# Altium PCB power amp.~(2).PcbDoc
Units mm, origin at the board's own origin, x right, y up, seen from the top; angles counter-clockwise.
Board outline 188.72 x 72.39 mm, 2 copper layers (Top Layer, Bottom Layer); 34 components, 39 nets, 124 pads, 0 vias.
Unrouted connection lines stored in the file: 65.
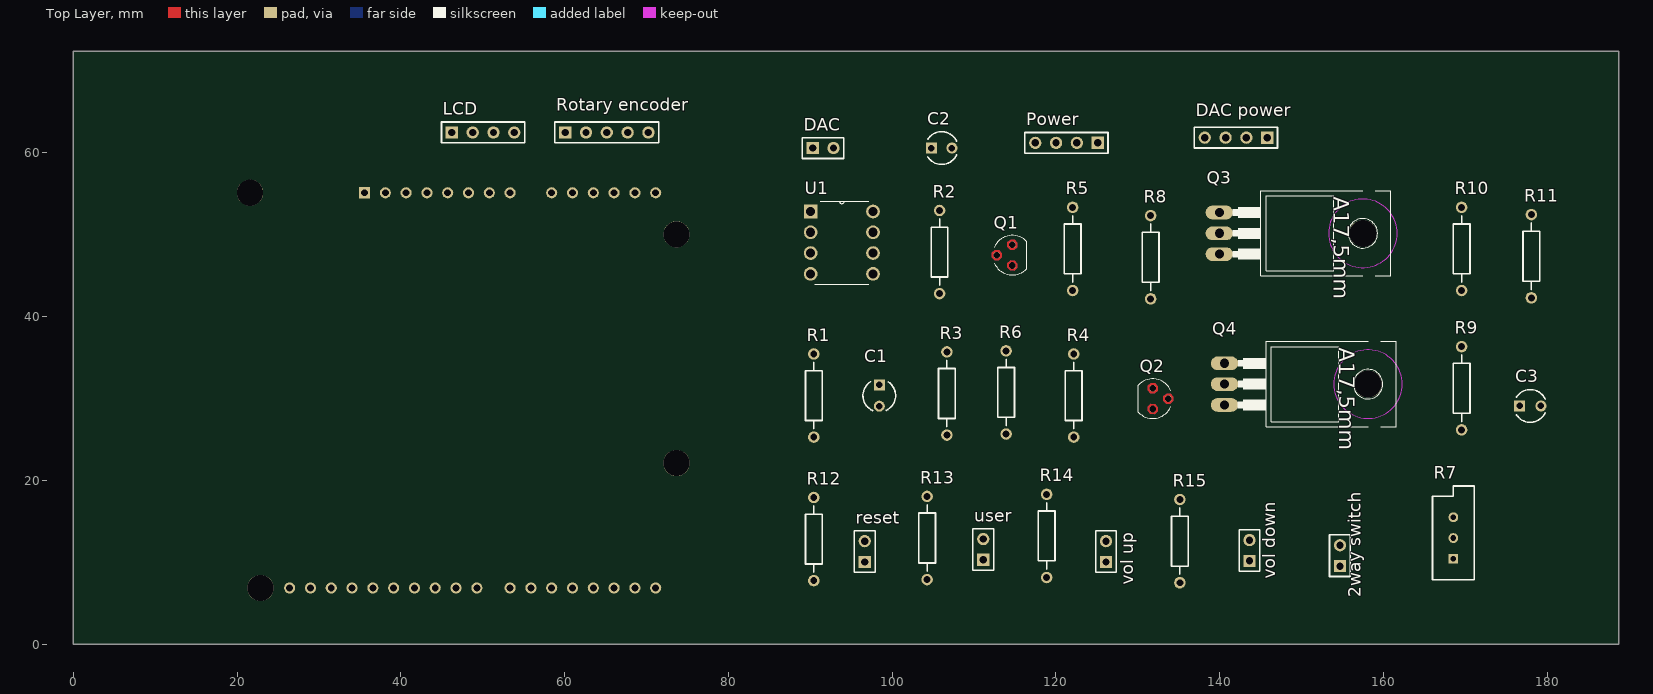
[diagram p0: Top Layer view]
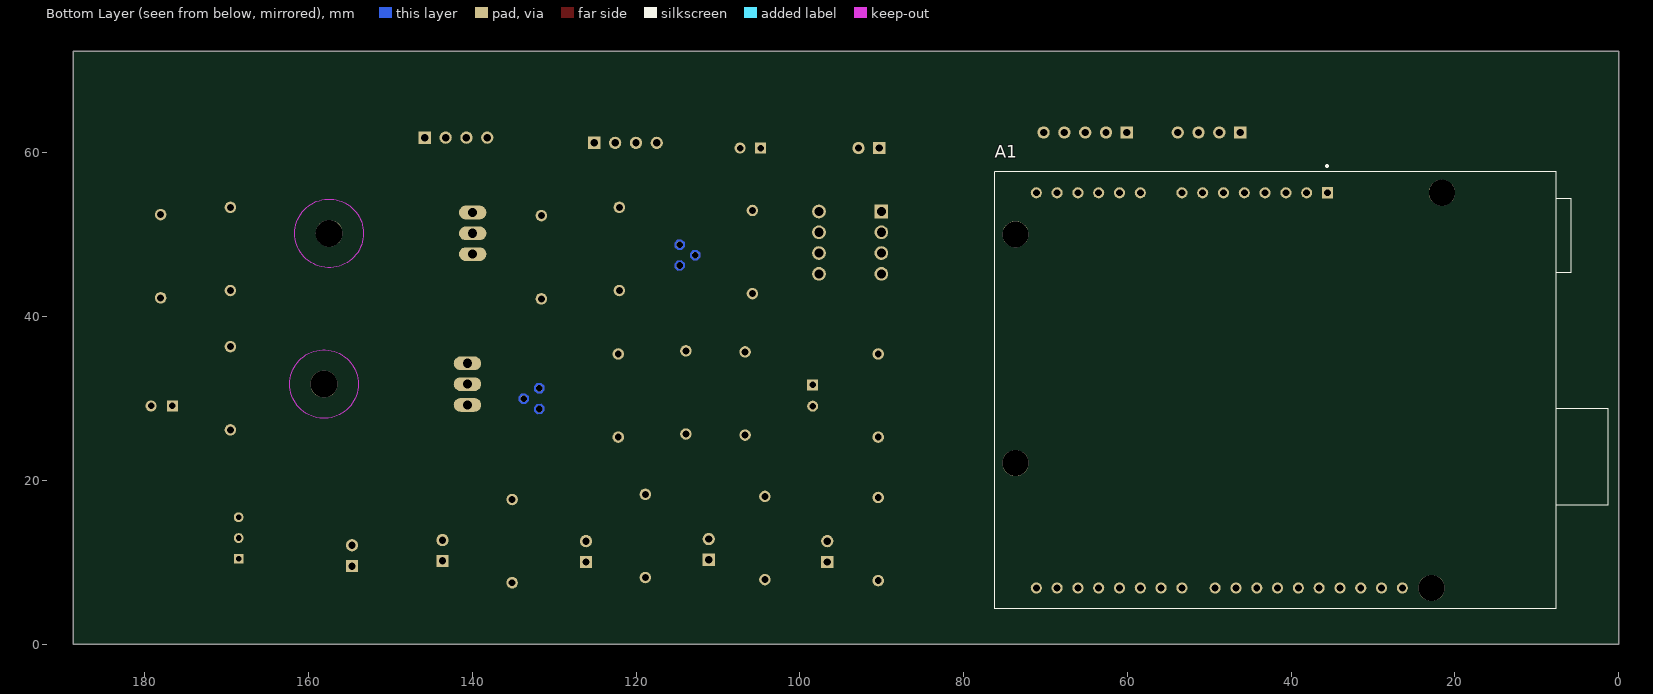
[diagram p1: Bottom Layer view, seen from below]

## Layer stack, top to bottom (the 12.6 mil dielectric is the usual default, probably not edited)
Top Solder: solder mask 0.0102, Solder Resist, Dk 3.5
Top Layer: signal copper 0.0356
Dielectric 1: dielectric 0.32, FR-4, Dk 4.8
Bottom Layer: signal copper 0.0356
Bottom Solder: solder mask 0.0102, Solder Resist, Dk 3.5

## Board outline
0,0 188.722,0 188.722,72.39 0,72.39

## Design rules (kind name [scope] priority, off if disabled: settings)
Clearance [All] p1: gap=0.254 ignorepadtopadclearanceinfootprint=FALSE except(0: Arc-Hole Track-Hole SMDPad-Hole THPad-Hole Via-Hole Fill-Hole Poly-Hole Region-Hole Text-Hole; 0.508: Arc-Arc Arc-Track Arc-THPad Track-Track Track-THPad)
PolygonConnect [All] p1: connectstyle=Relief reliefconductorwidth=0.254 reliefentries=4 polygonreliefangle="90 Angle" airgapwidth=0.254
RoutingLayers [All] p1: top layer_v5=TRUE bottom layer_v5=FALSE
RoutingVias [All] p1: holewidth=0.711 width=1.27 viastyle="Through Hole" minholewidth=0.711 minwidth=1.27 maxholewidth=0.711 maxwidth=1.27
SolderMaskExpansion [All] p1: expansion=0.102
Width [All] p1: maxlimit=0.813 minlimit=0.254 preferedwidth=0.762 toplayer_minwidth=0.711 bottomlayer_maxwidth=0.254 bottomlayer_prefwidth=0.254 minimp=50.000000 maximp=50.000000 favimp=50.000000
29 further rules are at their usual default settings.

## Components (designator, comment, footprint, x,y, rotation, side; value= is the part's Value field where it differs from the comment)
"2way switch" "Header 2" HDR1X2 154.686,9.525 r90 top
A1 "ARDUINO_UNO_REV3_DEVELOPMENT_BOARD" *ARDUINO_UNO_REV3_DEVELOPMENT_BOARD 41.91,30.988 r270 bottom
C1 "Cap2" CAPR5-4X5#1 98.425,30.353 r270 top value=0.01uF
C2 "Cap2" CAPR5-4X5#2 106.045,60.579 r0 top value=47uF
C3 "Cap2" CAPR5-4X5#1 177.927,29.083 r0 top value=33uF
DAC "Header 2" HDR1X2 90.297,60.579 r0 top
"DAC power" "Header 4" HDR1X4 145.796,61.849 r180 top
LCD "Header 4" HDR1X4 46.228,62.484 r0 top
Power "Header 4" HDR1X4 125.095,61.214 r180 top
Q1 "BC640" *SOT54D_BC640(Primary) 114.681,47.498 r90 top
Q2 "BC639" *SOT54D_BC639(Primary) 131.826,29.972 r270 top
Q3 "TIP125" *TO220 146.304,50.165 r270 top
Q4 "TIP120" *TO220AH_TIP120(Primary) 146.939,31.75 r270 top
R1 "Res2" AXIAL-0.4 90.424,30.353 r90 top value=12K
R2 "Res2" AXIAL-0.4 105.791,47.879 r270 top value=22K
R3 "Res2" AXIAL-0.4 106.68,30.607 r90 top value=15K
R4 "Res2" AXIAL-0.4 122.174,30.353 r270 top value=2.2K
R5 "Res2" AXIAL-0.4 122.047,48.26 r270 top value=4.7K
R6 "Res2" AXIAL-0.4 113.919,30.734 r90 top value=4.7K
R7 "RPot" VR5 168.529,12.954 r90 top value=10K
R8 "Res2" AXIAL-0.4 131.572,47.244 r90 top value=10K
R9 "Res2" AXIAL-0.4 169.545,31.242 r270 top value=1
R10 "Res2" AXIAL-0.4 169.545,48.26 r270 top value=1
R11 "Res2" AXIAL-0.4 178.054,47.371 r270 top value=1K
R12 "Res2" AXIAL-0.4 90.424,12.827 r270 top value=12K
R13 "Res2" AXIAL-0.4 104.267,12.954 r270 top value=12K
R14 "Res2" AXIAL-0.4 118.872,13.208 r270 top value=12K
R15 "Res2" AXIAL-0.4 135.128,12.573 r270 top value=12K
reset "Header 2" HDR1X2 96.647,10.033 r90 top
"Rotary encoder" "Header 5" HDR1X5 60.071,62.484 r0 top
U1 "TL071CP" *DIP254P762X508-8 97.663,45.212 r0 top
user "Header 2" HDR1X2 111.125,10.287 r90 top
"vol down" "Header 2" HDR1X2 143.637,10.16 r90 top
"vol up" "Header 2" HDR1X2 126.111,10.033 r90 top

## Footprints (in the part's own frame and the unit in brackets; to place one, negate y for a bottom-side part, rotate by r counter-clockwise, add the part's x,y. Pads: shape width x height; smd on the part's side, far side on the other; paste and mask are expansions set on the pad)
*ARDUINO_UNO_REV3_DEVELOPMENT_BOARD [mm]
  rect 1.358x1.358 hole 0.85: 1(-24.13,6.35)
  round 1.358 hole 0.85: 2(-24.13,3.81) 3(-24.13,1.27) 4(-24.13,-1.27) 5(-24.13,-3.81) 6(-24.13,-6.35) 7(-24.13,-8.89) 8(-24.13,-11.43) 9(-24.13,-16.51) 10(-24.13,-19.05) 11(-24.13,-21.59) 12(-24.13,-24.13) 13(-24.13,-26.67) 14(-24.13,-29.21) 15(24.13,-29.21) 16(24.13,-26.67) 17(24.13,-24.13) 18(24.13,-21.59) 19(24.13,-19.05) 20(24.13,-16.51) 21(24.13,-13.97) 22(24.13,-11.43) 23(24.13,-7.366) 24(24.13,-4.826) 25(24.13,-2.286) 26(24.13,0.254) 27(24.13,2.794) 28(24.13,5.334) 29(24.13,7.874) 30(24.13,10.414) 31(24.13,12.954) 32(24.13,15.494)
  round 3.2 hole 3.2 unplated: None(-24.13,20.32) None(-19.05,-31.75) None(8.89,-31.75) None(24.13,19.05)
  silkscreen extent -27.52,-34.29 26.67,40.64
*DIP254P762X508-8 [mil]
  rect 66x66 hole 44: 1(-300,300)
  round 66 hole 44: 2(-300,200) 3(-300,100) 4(-300,0) 5(0,0) 6(0,100) 7(0,200) 8(0,300)
  silkscreen extent -280,-50 -20,350
*SOT54D_BC639(Primary) [mil]
  round 32 hole 32: B(50,0) C(0,75) E(-50,0)
  Top Layer region: -25.57,8.89 -39.01,23.56 -58.89,24.43 -73.56,10.99 -74.43,-8.89 -60.99,-23.56 -41.11,-24.43 -26.44,-10.99
  Top Layer region: 24.43,83.89 10.99,98.56 -8.89,99.43 -23.56,85.99 -24.43,66.11 -10.99,51.44 8.89,50.57 23.56,64.01
  Top Layer region: 74.43,8.89 60.99,23.56 41.11,24.43 26.44,10.99 25.57,-8.89 39.01,-23.56 58.89,-24.43 73.56,-10.99
  Bottom Layer region: -25.57,8.89 -39.01,23.56 -58.89,24.43 -73.56,10.99 -74.43,-8.89 -60.99,-23.56 -41.11,-24.43 -26.44,-10.99
  Bottom Layer region: 24.43,83.89 10.99,98.56 -8.89,99.43 -23.56,85.99 -24.43,66.11 -10.99,51.44 8.89,50.57 23.56,64.01
  Bottom Layer region: 74.43,8.89 60.99,23.56 41.11,24.43 26.44,10.99 25.57,-8.89 39.01,-23.56 58.89,-24.43 73.56,-10.99
  Multi-Layer region: -25.57,8.89 -39.01,23.56 -58.89,24.43 -73.56,10.99 -74.43,-8.89 -60.99,-23.56 -41.11,-24.43 -26.44,-10.99
  Multi-Layer region: 24.43,83.89 10.99,98.56 -8.89,99.43 -23.56,85.99 -24.43,66.11 -10.99,51.44 8.89,50.57 23.56,64.01
  Multi-Layer region: 74.43,8.89 60.99,23.56 41.11,24.43 26.44,10.99 25.57,-8.89 39.01,-23.56 58.89,-24.43 73.56,-10.99
  silkscreen extent -95,-70 95,87
*SOT54D_BC640(Primary) [mil]
  round 32 hole 32: B(50,0) C(0,75) E(-50,0)
  Top Layer region: -25.57,8.89 -39.01,23.56 -58.89,24.43 -73.56,10.99 -74.43,-8.89 -60.99,-23.56 -41.11,-24.43 -26.44,-10.99
  Top Layer region: 24.43,83.89 10.99,98.56 -8.89,99.43 -23.56,85.99 -24.43,66.11 -10.99,51.44 8.89,50.57 23.56,64.01
  Top Layer region: 74.43,8.89 60.99,23.56 41.11,24.43 26.44,10.99 25.57,-8.89 39.01,-23.56 58.89,-24.43 73.56,-10.99
  Bottom Layer region: -25.57,8.89 -39.01,23.56 -58.89,24.43 -73.56,10.99 -74.43,-8.89 -60.99,-23.56 -41.11,-24.43 -26.44,-10.99
  Bottom Layer region: 24.43,83.89 10.99,98.56 -8.89,99.43 -23.56,85.99 -24.43,66.11 -10.99,51.44 8.89,50.57 23.56,64.01
  Bottom Layer region: 74.43,8.89 60.99,23.56 41.11,24.43 26.44,10.99 25.57,-8.89 39.01,-23.56 58.89,-24.43 73.56,-10.99
  Multi-Layer region: -25.57,8.89 -39.01,23.56 -58.89,24.43 -73.56,10.99 -74.43,-8.89 -60.99,-23.56 -41.11,-24.43 -26.44,-10.99
  Multi-Layer region: 24.43,83.89 10.99,98.56 -8.89,99.43 -23.56,85.99 -24.43,66.11 -10.99,51.44 8.89,50.57 23.56,64.01
  Multi-Layer region: 74.43,8.89 60.99,23.56 41.11,24.43 26.44,10.99 25.57,-8.89 39.01,-23.56 58.89,-24.43 73.56,-10.99
  silkscreen extent -95,-70 95,87
*TO220 [mil]
  oval 66x132 hole 44: 1(-100,-250) 2(0,-250) 3(100,-250)
  round 130 hole 130 unplated: None(0,440)
  Keep-Out Layer circle w0: c0,440 r165
  Keep-Out Layer circle w0: c0,440 r165
  Keep-Out Layer circle w0: c0,440 r165
  Keep-Out Layer circle w0: c0,440 r165
  Keep-Out Layer circle w0: c0,440 r165
  Keep-Out Layer circle w0: c0,440 r165
  silkscreen extent -205,-185 205,575
*TO220AH_TIP120(Primary) [mil]
  oval 66x132 hole 44: B(-100,-250) C(0,-250) E(100,-250)
  round 130 hole 130 unplated: None(0,440)
  Keep-Out Layer circle w0: c0,440 r165
  Keep-Out Layer circle w0: c0,440 r165
  Keep-Out Layer circle w0: c0,440 r165
  Keep-Out Layer circle w0: c0,440 r165
  Keep-Out Layer circle w0: c0,440 r165
  Keep-Out Layer circle w0: c0,440 r165
  silkscreen extent -205,-185 205,575
AXIAL-0.4 [mm] "Axial Device, Thru-Hole; 2 Leads; 0.4 in Pin Spacing"
  round 1.4 hole 0.85: 1(-5.08,0) 2(5.08,0)
  silkscreen extent -4.06,-1.02 4.06,1.02
CAPR5-4X5#1 [mm] "Capacitor; 2 Leads"
  rect 1.35x1.35 hole 0.8: 1(-1.3,0)
  round 1.35 hole 0.8: 2(1.3,0)
  silkscreen extent -1.69,-2 1.82,2
CAPR5-4X5#2 [mm] "Capacitor; 2 Leads"
  rect 1.35x1.35 hole 0.8: 1(-1.25,0)
  round 1.35 hole 0.8: 2(1.25,0)
  silkscreen extent -1.69,-2 1.82,2
HDR1X2 [mm] "Connector; Header; 2 Position"
  rect 1.5x1.5 hole 0.9: 1(0,0)
  round 1.5 hole 0.9: 2(2.54,0)
  silkscreen extent -1.27,-1.27 3.81,1.27
HDR1X4 [mm] "Connector; Header; 4 Position"
  rect 1.5x1.5 hole 0.9: 1(0,0)
  round 1.5 hole 0.9: 2(2.54,0) 3(5.08,0) 4(7.62,0)
  silkscreen extent -1.27,-1.27 8.89,1.27
HDR1X5 [mm] "Connector; Header; 5 Position"
  rect 1.5x1.5 hole 0.9: 1(0,0)
  round 1.5 hole 0.9: 2(2.54,0) 3(5.08,0) 4(7.62,0) 5(10.16,0)
  silkscreen extent -1.27,-1.27 11.43,1.27
VR5 [mm] "Thru-Hole; 3 Leads"
  rect 1.2x1.2 hole 0.7: 1(-2.54,0)
  round 1.2 hole 0.7: 2(0,0) 3(2.54,0)
  silkscreen extent -5.08,-2.54 6.35,2.54

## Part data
"2way switch" DAC reset user "vol down" "vol up": "Header, 2-Pin"
A1: "Plated Through Hole Protoboard Arduino Mega Platform Evaluation Expansion Board", Package=None
C1 C2 C3: "Capacitor"
"DAC power" LCD Power: "Header, 4-Pin"
Q1: "Bipolar _BJT_ Transistor PNP 80V 500mA 150MHz 625mW Through Hole TO-92-3", Package="TO-92 Continental Device"
Q2: "Bipolar _BJT_ Transistor NPN 80V 1A 200MHz 625mW Through Hole TO-92-3", Package="TO-92 Continental Device"
Q3: "Bipolar _BJT_ Transistor PNP - Darlington 60V 5A 2W Through Hole TO-220-3", Package="TO-220 Fairchild Semiconductor"
Q4: "Bipolar _BJT_ Transistor NPN - Darlington 60V 5A 2W Through Hole TO-220-3", Package="TO-220-3 Bourns"
R1 R2 R3 R4 R5 R6 R8 R9 R10 R11 R12 R13 R14 R15: "Resistor"
R7: "Potentiometer"
"Rotary encoder": "Header, 5-Pin"
U1: "J-FET Amplifier 1 Circuit 8-PDIP", Package="DIP-8 Texas Instruments"

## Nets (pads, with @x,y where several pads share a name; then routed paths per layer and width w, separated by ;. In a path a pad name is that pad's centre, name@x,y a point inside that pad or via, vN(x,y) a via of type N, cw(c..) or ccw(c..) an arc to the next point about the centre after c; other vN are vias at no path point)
+5V: "DAC power.4" "Rotary encoder.2" A1.5 LCD.2 R12.1 R13.1 R14.1 R15.1
+15V: "DAC power.2" Power.1 Q4.C R2.2 R8.2 U1.7
-15V: "DAC power.3" Power.4 Q3.2 R3.1 R6.1 U1.4
A0: A1.9
A1: A1.10
A2: A1.11
A3: A1.12
CLK: "Rotary encoder.5" A1.17
D0: A1.15
D1: A1.16
D4: A1.19 R12.2 reset.1
D5: A1.20
D6: A1.21 R1.1
D7: A1.22 R13.2 user.1
D8: "vol up.1" A1.23 R14.2
D9: A1.24
D10: A1.25
D11: A1.26
D12: "vol down.1" A1.27 R15.2
D13: A1.28
"DAC in": DAC.1 U1.2 U1.6
"DAC out": C2.1 DAC.2
DT: "Rotary encoder.4" A1.18
GND: "2way switch.2" "DAC power.1" "Rotary encoder.1" "vol down.2" "vol up.2" A1.6 C1.2 LCD.1 Power.2 Power.3 reset.2 user.2
NetC1_1: C1.1 R1.2 U1.3
NetC2_2: C2.2 Q1.B R2.1 R3.2
NetC3_1: C3.1 R9.1 R10.2
NetC3_2: C3.2 R11.2
NetQ1_C: Q1.C R6.2
NetQ1_E: Q1.E Q2.E Q3.1 R5.1
NetQ2_B: Q2.B R4.1 R5.2
NetQ2_C: Q2.C Q4.B R7.2 R8.1
NetQ3_3: Q3.3 R10.1
NetQ4_E: Q4.E R9.2
NetR4_2: R4.2 R7.1
Out: "2way switch.1" R11.1
SCL: A1.14 LCD.4
SDA: A1.13 LCD.3
SW: "Rotary encoder.3"
pads on no net: A1.1 A1.2 A1.3 A1.4 A1.7 A1.8 A1.29 A1.30 A1.31 A1.32 A1.None Q3.None Q4.None R7.3 U1.1 U1.5 U1.8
